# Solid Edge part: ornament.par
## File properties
Author: user
Template: iso part.par
Last saved by: user
Revision: 2
Application: Solid Edge
Accuracy: 0.990
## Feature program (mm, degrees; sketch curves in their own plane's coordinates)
sketch for "unnamed RevolvedProtrusion 1" plane through (0, 0, 0) normal (0, -1, 0) x-axis (1, 0, 0)
  line (100, 0) -> (0, 500)
  line (0, 0) -> (0, 500)
  line (0, 0) -> (100, 0)
revolve "unnamed RevolvedProtrusion 1" add finite 360 deg
sketch for "unnamed Cutout 1" plane through (0, 0, 0) normal (0, -1, 0) x-axis (1, 0, 0)
  line (60, 350) -> (-60, 350)
extrude "unnamed Cutout 1" cut finite 300 symmetric
sketch for "Hole_1" plane through (0, 0, 350) normal (0, 0, 1) x-axis (1, 0, 0)
  hole centre (0, 0) bore radius 10
hole "Hole_1" diameter 20 through
sketch for "Hole_2" plane through (0, 0, 0) normal (0, 0, -1) x-axis (1, 0, 0)
  hole centre (0, 0) bore radius 50
hole "Hole_2" diameter 100 finite
sketch for "Hole_3" plane through (0, 0, 50) normal (0, 0, -1) x-axis (1, 0, 0)
  hole centre (0, 0) bore radius 30
hole "Hole_3" diameter 60 finite
fillet "Round_1" radius 5
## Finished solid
Body 1: solid body, 9 faces, 9 edges, 0 vertices.
  Faces by surface: plane 4, cylinder 3, cone 1, torus 1
  Edges by curve: circle 9
Bounding box of the edges (mm; curved faces can reach further): 200.000 x 200.000 x 350.000, from (-100, -100, 0) to (100, 100, 350).
Cylindrical faces by radius (mm): R10 x1, R30 x1, R50 x1
Conical faces (half-angle, radius in mm at the cone's reference point): 11.3099 deg R100 x1
Toroidal faces (ring radius, tube radius in mm): R25.901 r5 x1
Planar faces by outward normal: +z 1, -z 3
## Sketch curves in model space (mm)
line (60, 0, 350) -> (-60, 0, 350)
line (100, 0, 0) -> (0, 0, 500)
line (0, 0, 0) -> (100, 0, 0)
line (0, 0, 0) -> (0, 0, 500)
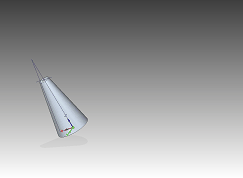
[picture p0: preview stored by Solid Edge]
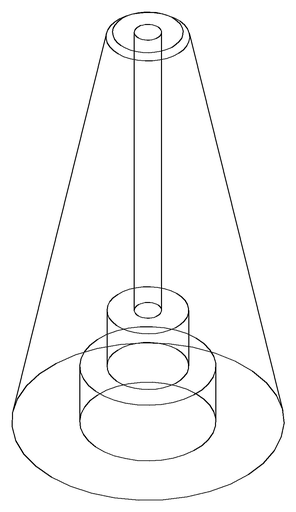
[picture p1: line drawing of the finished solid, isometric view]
